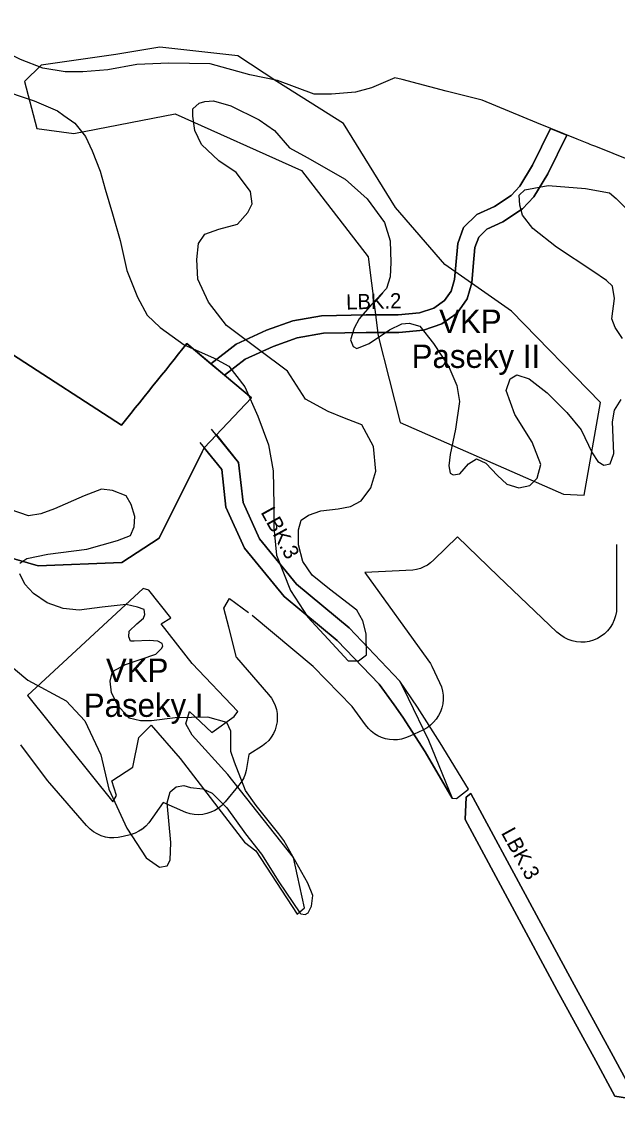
# Model space of a CAD drawing. Extents: x -555426 to -553015, y -1186745 to -1182595.
# Drawn here: x -554746 to -554236, y -1183523 to -1182595 of the extents above; entities that cross this region are included whole.
import ezdxf

# ---------------------------------------------------------------- set-up
doc = ezdxf.new("R2010")
doc.units = 0
for name, color, linetype in [('Level 10', 7, 'Continuous'), ('Level 12', 7, 'Continuous'), ('Level 14', 7, 'Continuous'), ('Level 7', 7, 'Continuous'), ('svahove_deformace', 7, 'Continuous'), ('USES_ID', 7, 'Continuous'), ('USES_LBC_stav', 7, 'Continuous'), ('USES_LBK_navrh', 7, 'Continuous'), ('USES_LBK_stav', 7, 'Continuous')]:
    doc.layers.add(name, color=color, linetype=linetype)

msp = doc.modelspace()

# ---------------------------------------------------------------- linework, layer by layer
at = {"layer": 'Level 10'}
for points in [[(-554560.63, -1182624.59), (-554627.3, -1182617.18), (-554664.88, -1182623.35), (-554729.04, -1182632.47), (-554743.19, -1182646.63), (-554732.61, -1182686.85), (-554700.86, -1182691.08), (-554614.08, -1182674.15), (-554506.13, -1182722.83), (-554448.98, -1182796.91), (-554440.51, -1182864.65), (-554421.46, -1182938.73), (-554281.76, -1183000.11), (-554263.87, -1183001.06), (-554249.88, -1182921.77), (-554326.21, -1182843.48), (-554383.36, -1182803.26), (-554425.69, -1182754.58), (-554470.14, -1182682.61), (-554527.29, -1182646.63), (-554560.63, -1182624.59)], [(-554599.69, -1183145.33), (-554626.25, -1183111.42), (-554617.78, -1183106.13), (-554636.85, -1183082.49), (-554641.56, -1183080.97), (-554740.55, -1183172.81), (-554667.52, -1183263.82), (-554664.35, -1183258.53), (-554668.58, -1183245.83), (-554650.59, -1183234.19), (-554645.3, -1183208.79), (-554634.71, -1183198.21), (-554609.84, -1183226.6), (-554554.81, -1183298.56), (-554545.04, -1183305.89), (-554509.83, -1183360.13), (-554503.48, -1183354.84), (-554509.51, -1183327.35), (-554513, -1183311.45), (-554569.1, -1183240.54), (-554599.79, -1183206.67), (-554605.08, -1183197.15), (-554601.9, -1183186.57), (-554582.85, -1183204.56), (-554563.61, -1183190.81), (-554560.63, -1183186.57), (-554599.69, -1183145.33)]]:
    msp.add_lwpolyline(points, dxfattribs=at)
at = {"layer": 'Level 12'}
for points in [[(-554278.84, -1182692.52), (-554292.75, -1182686.82), (-554308.22, -1182718.41), (-554319.19, -1182736.19), (-554326.62, -1182744.22), (-554340.88, -1182753.58), (-554355.87, -1182760.59), (-554367.23, -1182771.68), (-554372.32, -1182785.51), (-554374.03, -1182803.89), (-554374.9, -1182816.33), (-554377.79, -1182826.15), (-554383.47, -1182834.21), (-554392.86, -1182840.73), (-554404.9, -1182844.94), (-554423.27, -1182846.67), (-554450.71, -1182846.67), (-554488.79, -1182847.37), (-554513.54, -1182851.74), (-554535.95, -1182859.69), (-554561.97, -1182871.74), (-554583.66, -1182888.49)], [(-554571.89, -1182898.35), (-554554.14, -1182884.64), (-554530.27, -1182873.59), (-554509.71, -1182866.3), (-554487.34, -1182862.35), (-554450.57, -1182861.67), (-554422.57, -1182861.67), (-554401.67, -1182859.7), (-554385.98, -1182854.21), (-554372.74, -1182845.02), (-554364.1, -1182832.76), (-554360.05, -1182819.01), (-554359.08, -1182805.11), (-554357.56, -1182788.85), (-554354.33, -1182780.04), (-554347.21, -1182773.11), (-554333.55, -1182766.72), (-554316.86, -1182755.75), (-554307.19, -1182745.3), (-554295.07, -1182725.66), (-554278.84, -1182692.52)], [(-554373.37, -1183261.05), (-554363.18, -1183253.13), (-554387.43, -1183213.22), (-554406.75, -1183182.83), (-554421.72, -1183160.34), (-554465.31, -1183114.69), (-554510.26, -1183077.44), (-554542.02, -1183038.4), (-554556.09, -1183007.25), (-554559.91, -1182973), (-554582.98, -1182944.4)], [(-554593.01, -1182955.85), (-554574.33, -1182979.01), (-554570.74, -1183011.26), (-554554.89, -1183046.35), (-554520.97, -1183088.05), (-554475.52, -1183125.71), (-554439.49, -1183162.97), (-554426.66, -1183180.83), (-554419.18, -1183191.24), (-554400.25, -1183221.01), (-554377.12, -1183260.83), (-554373.37, -1183261.05)], [(-554365.04, -1183259.86), (-554366.04, -1183279.01), (-554323.69, -1183357.57), (-554287.45, -1183424.85), (-554254.12, -1183485.9), (-554237.68, -1183516.1), (-554192.54, -1183523.12), (-554175.73, -1183511.81), (-554163.01, -1183503.48), (-554155.35, -1183498.48), (-554147.85, -1183491.97), (-554127.17, -1183474.65), (-554115.67, -1183466.95), (-554110.58, -1183463.31)], [(-554110.58, -1183463.31), (-554103.48, -1183456.27), (-554092.27, -1183445.06), (-554122.23, -1183453.2), (-554124.21, -1183454.61), (-554136.18, -1183462.63), (-554157.58, -1183480.55), (-554164.41, -1183486.48), (-554171.22, -1183490.93), (-554184.03, -1183499.31), (-554196.04, -1183507.39), (-554228.05, -1183502.41), (-554240.95, -1183478.72), (-554274.26, -1183417.7), (-554310.48, -1183350.45), (-554361.08, -1183256.6), (-554365.04, -1183259.86)]]:
    msp.add_lwpolyline(points, dxfattribs=at)
at = {"layer": 'Level 14'}
msp.add_lwpolyline([(-554788.83, -1183044.98), (-554731.54, -1183061.61), (-554659.93, -1183058.83), (-554628.05, -1183038.04), (-554591, -1182963.93), (-554589.32, -1182960.43), (-554548.94, -1182917.58), (-554604.33, -1182871.18), (-554607.57, -1182875.37), (-554611.33, -1182880.08), (-554615.1, -1182884.8), (-554618.76, -1182889.39), (-554622.34, -1182893.87), (-554625.97, -1182898.29), (-554629.38, -1182902.63), (-554633.35, -1182907.44), (-554637.08, -1182912.33), (-554640.7, -1182916.69), (-554644.85, -1182921.99), (-554648.51, -1182926.36), (-554652.29, -1182931.05), (-554660.11, -1182940.98), (-554753.5, -1182880.52)], dxfattribs=at)
at = {"layer": 'Level 7'}
for points in [[(-554236.35, -1183043.25), (-554236.32, -1183061.41), (-554236.18, -1183096.46), (-554236.44, -1183100.74), (-554237.1, -1183104.36), (-554238.21, -1183107.87), (-554239.74, -1183111.22), (-554241.67, -1183114.35), (-554243.97, -1183117.23), (-554246.6, -1183119.8), (-554249.53, -1183122.03), (-554252.71, -1183123.88), (-554256.1, -1183125.34), (-554259.63, -1183126.36), (-554263.27, -1183126.94), (-554266.95, -1183127.07), (-554270.62, -1183126.75), (-554274.22, -1183125.98), (-554277.7, -1183124.78), (-554281, -1183123.16), (-554284.08, -1183121.15), (-554287.36, -1183118.37), (-554337.51, -1183070.38), (-554372.49, -1183036.91), (-554392.63, -1183056.57), (-554395.55, -1183059.12), (-554398.28, -1183061.01), (-554401.2, -1183062.59), (-554404.27, -1183063.83), (-554407.47, -1183064.73), (-554410.74, -1183065.27), (-554451.85, -1183067.4), (-554397.75, -1183142.29), (-554395.69, -1183145.47), (-554394.51, -1183147.7), (-554387.87, -1183161.54), (-554386.27, -1183165.46), (-554385.32, -1183168.95), (-554384.79, -1183172.53), (-554384.71, -1183176.15), (-554385.05, -1183179.75), (-554385.83, -1183183.28), (-554387.03, -1183186.7), (-554388.64, -1183189.94), (-554390.62, -1183192.97), (-554392.95, -1183195.74), (-554395.6, -1183198.2), (-554398.53, -1183200.33), (-554402.22, -1183202.38), (-554413.16, -1183207.63), (-554416.92, -1183209.17), (-554420.28, -1183210.11), (-554423.71, -1183210.65), (-554427.2, -1183210.79), (-554430.67, -1183210.53), (-554434.08, -1183209.86), (-554437.4, -1183208.81), (-554440.57, -1183207.37), (-554443.56, -1183205.58), (-554446.31, -1183203.45), (-554448.8, -1183201.02), (-554451.36, -1183197.86), (-554462.58, -1183182.25), (-554495.92, -1183147.77), (-554548.41, -1183104.06)], [(-554561.64, -1183140.12), (-554568.28, -1183114.25), (-554572.44, -1183098.02), (-554567.83, -1183089.67), (-554551.3, -1183101.51)], [(-554561.64, -1183140.12), (-554534.2, -1183171.82), (-554531.76, -1183175.06), (-554529.98, -1183178.11), (-554528.57, -1183181.36), (-554527.56, -1183184.75), (-554526.96, -1183188.23), (-554526.77, -1183191.76), (-554527, -1183195.29), (-554527.65, -1183198.77), (-554528.7, -1183202.15), (-554530.15, -1183205.37), (-554531.97, -1183208.41), (-554534.13, -1183211.2), (-554536.61, -1183213.73), (-554539.37, -1183215.94), (-554551.21, -1183223.3), (-554553.28, -1183236.96), (-554554.19, -1183240.21), (-554555.49, -1183243.32), (-554557.16, -1183246.25), (-554559.59, -1183249.52), (-554571.43, -1183263.77), (-554574.35, -1183266.88), (-554577.17, -1183269.22), (-554580.24, -1183271.18), (-554583.54, -1183272.76), (-554587, -1183273.92), (-554590.58, -1183274.64), (-554594.22, -1183274.91), (-554597.87, -1183274.73), (-554601.47, -1183274.11), (-554604.97, -1183273.05), (-554624.5, -1183264.36), (-554636.8, -1183281.94), (-554639.29, -1183284.68), (-554643.07, -1183287.9)], [(-554641.03, -1183286.37), (-554645.19, -1183289.09), (-554648.52, -1183290.7), (-554652.67, -1183292.08), (-554658.63, -1183293.69), (-554662.89, -1183294.55), (-554666.6, -1183294.84), (-554670.32, -1183294.66), (-554673.99, -1183294.02), (-554677.55, -1183292.93), (-554680.95, -1183291.41), (-554684.13, -1183289.48), (-554687.05, -1183287.17), (-554690.1, -1183284.07), (-554721.6, -1183247.76), (-554723.39, -1183245.53), (-554746.22, -1183215.07)]]:
    msp.add_lwpolyline(points, dxfattribs=at)
at = {"layer": 'svahove_deformace'}
for p, q in [((-554304.41, -1182682.05), (-554351.46, -1182662.7)), ((-554270.07, -1182696.11), (-554304.41, -1182682.05)), ((-554258.73, -1182700.57), (-554258.78, -1182700.55)), ((-554224.4, -1182714.16), (-554254.15, -1182702.37))]:
    msp.add_line(p, q, dxfattribs=at)
for points in [[(-554419.74, -1182644.94), (-554426.06, -1182643.29), (-554446.03, -1182652), (-554459.79, -1182655.7), (-554480.43, -1182657.29), (-554495.25, -1182657.29), (-554526.47, -1182645.65), (-554550.28, -1182640.89), (-554584.15, -1182631.36), (-554619.6, -1182630.83), (-554647.12, -1182631.89), (-554671.99, -1182636.65), (-554693.16, -1182638.24), (-554708.5, -1182638.24), (-554727.55, -1182635.06), (-554746.6, -1182627.66), (-554767.24, -1182617.6), (-554791.05, -1182600.67), (-554796.68, -1182595.29), (-554800.72, -1182601.14), (-554801.19, -1182601.82), (-554830.68, -1182628.91)], [(-554351.46, -1182662.7), (-554360.45, -1182660.38), (-554382.27, -1182654.75), (-554419.74, -1182644.94)], [(-554766.71, -1182652.53), (-554734.96, -1182663.11), (-554714.85, -1182671.58), (-554709.56, -1182675.81), (-554700.03, -1182682.16), (-554691.04, -1182693.8), (-554685.22, -1182705.97), (-554678.34, -1182723.44), (-554674.11, -1182738.78), (-554667.76, -1182759.95), (-554661.41, -1182782.7), (-554655.58, -1182808.63), (-554646.59, -1182831.39), (-554638.12, -1182846.73), (-554627.01, -1182857.31), (-554606.37, -1182872.13), (-554581.5, -1182883.24), (-554568.27, -1182890.65), (-554554.51, -1182908.11), (-554543.4, -1182933.51), (-554534.41, -1182957.86), (-554530.17, -1182980.08), (-554529.64, -1183009.71), (-554529.64, -1183028.76), (-554527.53, -1183052.58), (-554515.36, -1183082.74), (-554500.54, -1183105.49), (-554473.02, -1183135.66), (-554466.14, -1183143.07), (-554461.91, -1183143.07), (-554457.15, -1183143.07), (-554450.27, -1183137.77), (-554450.8, -1183119.78), (-554453.44, -1183108.67), (-554458.73, -1183099.67), (-554482.02, -1183081.68), (-554496.83, -1183069.51), (-554504.77, -1183057.87), (-554508.48, -1183043.58), (-554508.48, -1183030.88), (-554506.36, -1183022.41), (-554500.01, -1183018.18), (-554489.43, -1183014.48), (-554474.61, -1183012.89), (-554464.03, -1183010.77), (-554455.03, -1183006.01), (-554446.56, -1182994.9), (-554442.33, -1182980.61), (-554444.45, -1182959.44), (-554454.5, -1182940.92), (-554469.32, -1182935.1), (-554483.08, -1182929.28), (-554502.66, -1182918.7), (-554518, -1182894.89), (-554542.87, -1182876.36), (-554570.39, -1182855.73), (-554585.73, -1182835.62), (-554594.73, -1182816.04), (-554595.79, -1182799.11), (-554594.2, -1182785.35), (-554588.91, -1182777.41), (-554576.74, -1182773.18), (-554560.86, -1182768.94), (-554551.87, -1182758.89), (-554548.16, -1182751.48), (-554549.75, -1182740.9), (-554561.92, -1182724.49), (-554576.74, -1182714.44), (-554591.56, -1182700.68), (-554597.38, -1182688.51), (-554598.96, -1182676.34), (-554598.96, -1182669.99), (-554593.67, -1182665.23), (-554588.91, -1182663.64), (-554581.5, -1182663.11), (-554566.68, -1182667.34), (-554542.34, -1182679.51), (-554529.11, -1182688.51), (-554516.41, -1182703.33), (-554501.07, -1182711.79), (-554468.79, -1182730.31), (-554449.74, -1182747.25), (-554434.92, -1182767.36), (-554430.16, -1182783.23), (-554429.63, -1182801.75), (-554430.16, -1182813.92), (-554433.33, -1182823.98), (-554446.03, -1182837.74), (-554456.62, -1182849.91), (-554460.85, -1182857.84), (-554464.03, -1182867.9), (-554461.91, -1182873.72), (-554458.73, -1182875.31), (-554448.15, -1182871.07), (-554430.69, -1182859.43), (-554420.1, -1182854.14), (-554413.75, -1182853.61), (-554404.76, -1182856.26), (-554393.12, -1182871.07), (-554379.89, -1182891.18), (-554373.01, -1182907.06), (-554370.89, -1182920.81), (-554374.07, -1182944.63), (-554378.83, -1182966.32), (-554379.89, -1182975.85), (-554378.83, -1182982.2), (-554376.18, -1182983.79), (-554370.36, -1182982.73), (-554362.95, -1182974.26), (-554356.08, -1182970.03), (-554348.14, -1182973.73), (-554338.08, -1182984.31), (-554330.15, -1182991.72), (-554320.09, -1182994.9), (-554310.57, -1182992.78), (-554304.22, -1182986.43), (-554301.04, -1182974.79), (-554308.45, -1182955.74), (-554323.27, -1182931.93), (-554330.68, -1182911.29), (-554327.5, -1182901.24), (-554321.68, -1182898.06), (-554311.1, -1182901.24), (-554295.75, -1182913.41), (-554278.82, -1182930.34), (-554266.65, -1182945.16), (-554257.12, -1182964.74), (-554252.36, -1182972.14), (-554247.07, -1182975.32), (-554241.78, -1182974.26), (-554238.6, -1182965.26), (-554239.66, -1182938.28), (-554238.07, -1182928.22), (-554232.25, -1182919.23)], [(-554258.78, -1182700.55), (-554260.59, -1182699.84), (-554261.54, -1182699.47), (-554270.07, -1182696.11)], [(-554254.15, -1182702.37), (-554257.43, -1182701.08), (-554258.73, -1182700.57)], [(-554231.19, -1182866.84), (-554237.54, -1182857.31), (-554240.19, -1182849.91), (-554238.07, -1182832.44), (-554239.66, -1182821.86), (-554244.95, -1182817.1), (-554256.59, -1182809.16), (-554287.81, -1182788.52), (-554307.92, -1182772.65), (-554316.92, -1182761.01), (-554319.03, -1182752.54), (-554319.56, -1182744.07), (-554314.8, -1182739.31), (-554294.69, -1182735.61), (-554262.94, -1182738.25), (-554242.3, -1182741.96), (-554236.48, -1182746.72), (-554225.9, -1182757.83)], [(-554747.13, -1183059.46), (-554741.31, -1183055.22), (-554723.32, -1183051.52), (-554689.98, -1183047.29), (-554663.52, -1183039.88), (-554652.41, -1183035.64), (-554649.23, -1183028.24), (-554648.71, -1183019.24), (-554651.88, -1183009.19), (-554656.11, -1183001.78), (-554667.76, -1182997.01), (-554677.28, -1182995.96), (-554692.1, -1183001.78), (-554717.5, -1183012.89), (-554729.14, -1183017.12), (-554739.72, -1183018.71), (-554755.6, -1183013.42)], [(-554761.42, -1183142.01), (-554740.25, -1183159.47), (-554707.44, -1183177.46), (-554691.57, -1183194.39), (-554677.81, -1183223.5), (-554670.93, -1183253.13), (-554655.58, -1183286.47), (-554639.18, -1183311.87), (-554627.54, -1183319.81), (-554621.19, -1183318.75), (-554618.54, -1183313.99), (-554618.01, -1183298.64), (-554621.19, -1183264.77), (-554618.54, -1183255.25), (-554613.25, -1183251.02), (-554606.9, -1183249.96), (-554601.08, -1183251.54), (-554590.5, -1183252.6), (-554582.56, -1183256.31), (-554569.86, -1183269.01), (-554553.98, -1183291.23), (-554540.23, -1183308.69), (-554525.41, -1183332.51), (-554507.42, -1183358.97), (-554506.54, -1183359.86), (-554502.79, -1183360.44), (-554500.46, -1183359.06), (-554497.34, -1183353.35), (-554496.34, -1183344.1), (-554500.54, -1183333.57), (-554521.18, -1183297.05), (-554525.41, -1183291.23), (-554544.99, -1183266.89), (-554553.98, -1183254.19), (-554563.51, -1183229.85), (-554566.68, -1183220.85), (-554566.68, -1183212.39), (-554566.68, -1183203.39), (-554569.86, -1183195.98), (-554586.26, -1183191.22), (-554614.31, -1183191.75), (-554634.42, -1183194.39), (-554643.94, -1183194.39), (-554653.47, -1183192.28), (-554662.99, -1183181.69), (-554668.81, -1183170.58), (-554669.87, -1183160.53), (-554667.76, -1183152.06), (-554656.64, -1183146.24), (-554630.71, -1183137.24), (-554625.95, -1183132.48), (-554624.89, -1183130.37), (-554625.42, -1183128.25), (-554629.13, -1183126.13), (-554636.53, -1183125.6), (-554649.23, -1183126.13), (-554652.41, -1183126.13), (-554654, -1183122.43), (-554653.47, -1183117.67), (-554647.12, -1183111.31), (-554641.3, -1183106.55), (-554640.24, -1183103.38), (-554640.77, -1183099.14), (-554646.59, -1183097.03), (-554656.11, -1183094.91), (-554676.75, -1183097.03), (-554696.33, -1183099.67), (-554710.09, -1183098.09), (-554723.85, -1183093.32), (-554735.49, -1183085.39), (-554742.9, -1183077.45), (-554747.13, -1183068.45)]]:
    msp.add_lwpolyline(points, dxfattribs=at)
at = {"layer": 'USES_LBC_stav'}
msp.add_line((-554571.89, -1182898.35), (-554571.89, -1182898.35), dxfattribs=at)
for points in [[(-554753.5, -1182880.52), (-554660.11, -1182940.98), (-554652.29, -1182931.05), (-554648.51, -1182926.36), (-554644.85, -1182921.99), (-554640.7, -1182916.69), (-554637.08, -1182912.33), (-554633.35, -1182907.44), (-554629.38, -1182902.63), (-554625.97, -1182898.29), (-554622.34, -1182893.87), (-554618.76, -1182889.39), (-554615.1, -1182884.8), (-554611.33, -1182880.08), (-554607.57, -1182875.37), (-554604.33, -1182871.18), (-554583.66, -1182888.49), (-554571.89, -1182898.35)], [(-554571.89, -1182898.35), (-554548.94, -1182917.58), (-554589.32, -1182960.43), (-554591, -1182963.93), (-554628.05, -1183038.04), (-554659.93, -1183058.83), (-554731.54, -1183061.61), (-554788.83, -1183044.98), (-554853.67, -1182999.48)], [(-554571.89, -1182898.35), (-554571.89, -1182898.35)]]:
    msp.add_lwpolyline(points, dxfattribs=at)
at = {"layer": 'USES_LBK_navrh'}
for p, q in [((-554406.75, -1183182.83), (-554421.72, -1183160.34)), ((-554421.72, -1183160.34), (-554414.65, -1183175.07)), ((-554414.65, -1183175.07), (-554397.33, -1183211.12)), ((-554387.43, -1183213.22), (-554406.75, -1183182.83)), ((-554397.33, -1183211.12), (-554377.12, -1183260.83)), ((-554363.18, -1183253.13), (-554387.43, -1183213.22)), ((-554373.37, -1183261.05), (-554363.18, -1183253.13)), ((-554377.12, -1183260.83), (-554373.37, -1183261.05)), ((-554366.04, -1183279.01), (-554365.04, -1183259.86))]:
    msp.add_line(p, q, dxfattribs=at)
for points in [[(-554365.04, -1183259.86), (-554361.08, -1183256.6), (-554310.48, -1183350.45)], [(-554254.12, -1183485.9), (-554287.45, -1183424.85), (-554323.69, -1183357.57), (-554366.04, -1183279.01)], [(-554310.48, -1183350.45), (-554274.26, -1183417.7), (-554240.95, -1183478.72), (-554228.05, -1183502.41), (-554196.04, -1183507.39), (-554184.03, -1183499.31)], [(-554175.73, -1183511.81), (-554192.54, -1183523.12), (-554237.68, -1183516.1), (-554254.12, -1183485.9)]]:
    msp.add_lwpolyline(points, dxfattribs=at)
at = {"layer": 'USES_LBK_stav'}
for p, q in [((-554573.82, -1182896.74), (-554583.66, -1182888.49)), ((-554554.14, -1182884.64), (-554571.89, -1182898.35)), ((-554571.89, -1182898.35), (-554573.82, -1182896.74)), ((-554589.32, -1182960.43), (-554578.94, -1182949.41)), ((-554421.72, -1183160.34), (-554414.65, -1183175.07)), ((-554414.65, -1183175.07), (-554397.33, -1183211.12)), ((-554397.33, -1183211.12), (-554377.12, -1183260.83))]:
    msp.add_line(p, q, dxfattribs=at)
for points in [[(-554583.66, -1182888.49), (-554561.97, -1182871.74), (-554535.95, -1182859.69), (-554513.54, -1182851.74), (-554488.79, -1182847.37), (-554450.71, -1182846.67), (-554423.27, -1182846.67), (-554404.9, -1182844.94), (-554392.86, -1182840.73), (-554383.47, -1182834.21), (-554377.79, -1182826.15), (-554374.9, -1182816.33), (-554374.03, -1182803.89), (-554372.32, -1182785.51), (-554367.23, -1182771.68), (-554355.87, -1182760.59), (-554340.88, -1182753.58), (-554326.62, -1182744.22), (-554319.19, -1182736.19), (-554308.22, -1182718.41), (-554292.75, -1182686.82), (-554278.84, -1182692.52)], [(-554278.84, -1182692.52), (-554295.07, -1182725.66), (-554307.19, -1182745.3), (-554316.86, -1182755.75), (-554333.55, -1182766.72), (-554347.21, -1182773.11), (-554354.33, -1182780.04), (-554357.56, -1182788.85), (-554359.08, -1182805.11), (-554360.05, -1182819.01), (-554364.1, -1182832.76), (-554372.74, -1182845.02), (-554385.98, -1182854.21), (-554401.67, -1182859.7), (-554422.57, -1182861.67), (-554450.57, -1182861.67), (-554487.34, -1182862.35), (-554509.71, -1182866.3), (-554530.27, -1182873.59), (-554554.14, -1182884.64)], [(-554578.94, -1182949.41), (-554559.91, -1182973), (-554556.09, -1183007.25), (-554542.02, -1183038.4), (-554510.26, -1183077.44), (-554465.31, -1183114.69), (-554421.72, -1183160.34)], [(-554377.12, -1183260.83), (-554400.25, -1183221.01), (-554419.18, -1183191.24), (-554426.66, -1183180.83), (-554439.49, -1183162.97), (-554475.52, -1183125.71), (-554520.97, -1183088.05), (-554554.89, -1183046.35), (-554570.74, -1183011.26), (-554574.33, -1182979.01), (-554589.32, -1182960.43)]]:
    msp.add_lwpolyline(points, dxfattribs=at)

# ---------------------------------------------------------------- texts
at = {"layer": 'Level 10'}
for s, p in [('VKP', (-554388.19, -1182862.02)), ('Paseky II', (-554411.71, -1182892.02)), ('VKP', (-554673.49, -1183161.07)), ('Paseky I', (-554692.47, -1183191.07))]:
    msp.add_text(s, height=20, dxfattribs=at).set_placement(p)
at = {"layer": 'USES_ID'}
for s, rotation, p in [('LBK.2', 1.48896, (-554467.7, -1182842.04)), ('LBK.3', 298.68708, (-554541.27, -1183015.62)), ('LBK.3', 298.68708, (-554335.44, -1183290.45))]:
    msp.add_text(s, height=13, rotation=rotation, dxfattribs=at).set_placement(p)

doc.saveas('drawing.dxf')
